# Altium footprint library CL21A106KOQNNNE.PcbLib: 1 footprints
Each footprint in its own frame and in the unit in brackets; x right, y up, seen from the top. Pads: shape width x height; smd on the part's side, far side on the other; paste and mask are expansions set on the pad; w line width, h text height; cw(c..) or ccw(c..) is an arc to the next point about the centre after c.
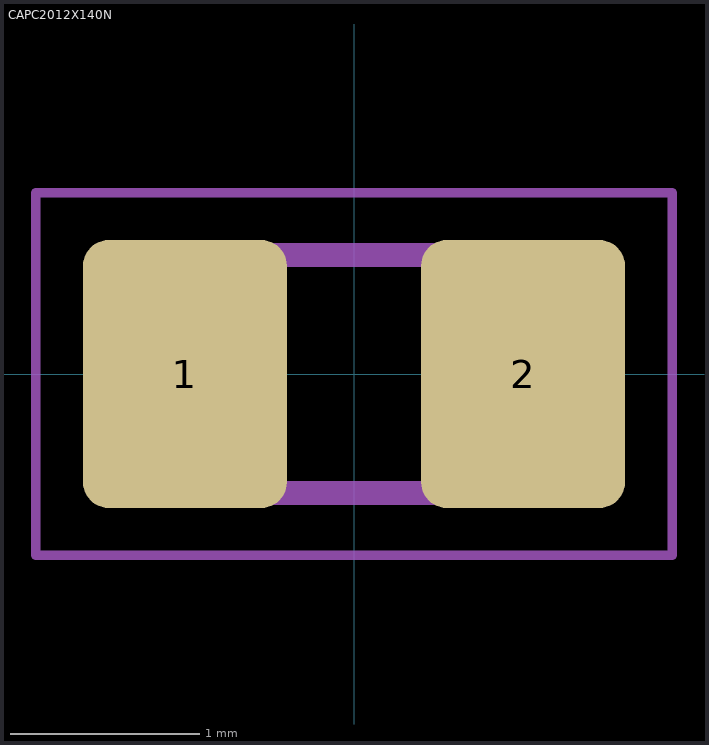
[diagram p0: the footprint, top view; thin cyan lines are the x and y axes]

## CAPC2012X140N [mm]
pads (2):
  rrect25% 1.08x1.42 smd: 1(-0.895,0) 2(0.895,0)
Assembly Top:
  lines w0.127: -1,-0.63 1,-0.63 1,0.63 -1,0.63 -1,-0.63
Courtyard Top:
  lines w0.05: -1.685,-0.96 1.685,-0.96 1.685,0.96 -1.685,0.96 -1.685,-0.96
3D body "step_temp.STEP": height 1.4, standoff 0, extent -1,-0.625 1,0.625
